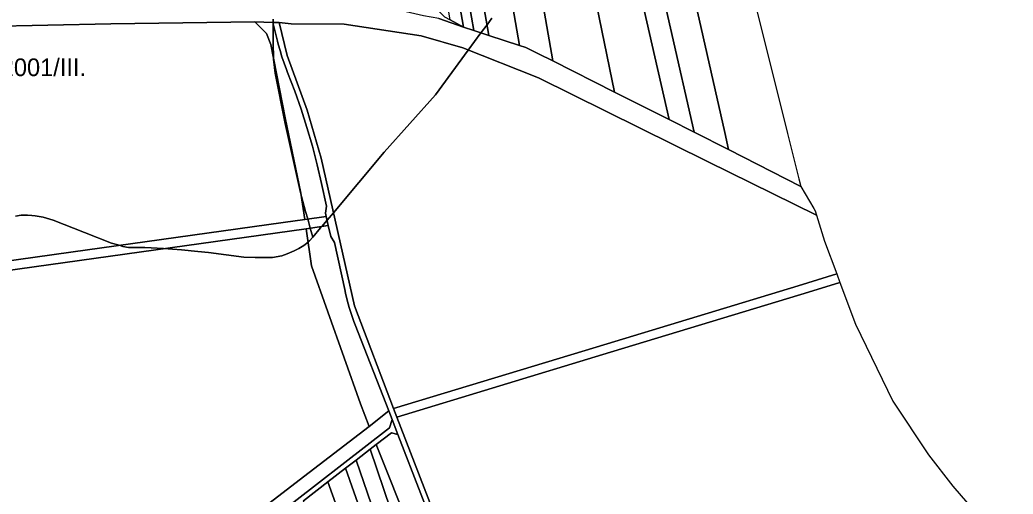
# Model space of a CAD drawing. Extents: x -521939 to -516426, y -1197857 to -1189551.
# Drawn here: x -518732 to -517887, y -1193407 to -1193004 of the extents above; entities that cross this region are included whole.
import ezdxf

# ---------------------------------------------------------------- set-up
doc = ezdxf.new("R2010")
doc.units = 0
for name, color, linetype in [('95560013', 7, 'Continuous'), ('95600013', 7, 'Continuous'), ('95610013', 7, 'Continuous'), ('95640013', 7, 'Continuous'), ('95660013', 7, 'Continuous')]:
    doc.layers.add(name, color=color, linetype=linetype)

msp = doc.modelspace()

# ---------------------------------------------------------------- linework, layer by layer
at = {"layer": '95560013'}
for points in [[(-518037.03, -1193220.36), (-518069.91, -1193230.34), (-518241.69, -1193282.48), (-518414.03, -1193334.79), (-518447.17, -1193247.47), (-518475.5, -1193121.86), (-518487.43, -1193081.14), (-518504.4, -1193034.52), (-518511.04, -1193006.71), (-518500.8, -1193007.81), (-518455.87, -1193008.08), (-518390.51, -1193017.79), (-518355.07, -1193028.15), (-518290.52, -1193053.74), (-518147.01, -1193124.62), (-518054.34, -1193170.39), (-518047.58, -1193192.34)], [(-517920.81, -1193457.64), (-517929.64, -1193459.01), (-517949.48, -1193456.49), (-517956.24, -1193459.13), (-517971.27, -1193470.3), (-517974.13, -1193472.43), (-518004.98, -1193496.63), (-518036.86, -1193524.72), (-518069.66, -1193560.73), (-518084.56, -1193581.03), (-518118.24, -1193594.97), (-518286.06, -1193664.43), (-518346.04, -1193509.88), (-518411.17, -1193342.06), (-518236.07, -1193288.88), (-518060.97, -1193235.7), (-518034.3, -1193227.6), (-518020.98, -1193262.98), (-517989.44, -1193328.34), (-517959.05, -1193374.1), (-517938.3, -1193400.82), (-517925.8, -1193415.15), (-517887.1, -1193453.28), (-517902.58, -1193457.64)], [(-518428.58, -1193365.29), (-518398.79, -1193439.68), (-518355.54, -1193549.59), (-518335.93, -1193621.27), (-518319.66, -1193697.29), (-518316.66, -1193706.74), (-518319.47, -1193708.05), (-518370.33, -1193556.63), (-518433.69, -1193369.25)], [(-518433.69, -1193369.25), (-518370.33, -1193556.63), (-518319.47, -1193708.05), (-518330.65, -1193713.26), (-518387.8, -1193546.85), (-518445.63, -1193378.46)], [(-518387.8, -1193546.85), (-518330.65, -1193713.26), (-518337.92, -1193716.66), (-518394.9, -1193555.25), (-518454.81, -1193385.54), (-518445.63, -1193378.46)], [(-518469.66, -1193396.97), (-518454.81, -1193385.54), (-518394.9, -1193555.25), (-518337.92, -1193716.66), (-518352.46, -1193723.43), (-518407.89, -1193569.03)], [(-518490.41, -1193413.05), (-518469.66, -1193396.97), (-518407.89, -1193569.03), (-518352.46, -1193723.43), (-518374.87, -1193733.88), (-518429.84, -1193581.24)]]:
    msp.add_lwpolyline(points, close=True, dxfattribs=at)
at = {"layer": '95600013'}
for points in [[(-518761.5, -1193009.97), (-518654.27, -1193007.7), (-518531.81, -1193005.92), (-518522.01, -1193015.8), (-518518.32, -1193025.36), (-518505.93, -1193087.66), (-518492.56, -1193151.65), (-518489.33, -1193173.91), (-518507.69, -1193176.48), (-518688.29, -1193201.76), (-518868.39, -1193226.97)], [(-518861.71, -1193234.11), (-518680.88, -1193208.8), (-518488.19, -1193181.83), (-518483.68, -1193213.33), (-518442.04, -1193330.76), (-518434.69, -1193349.86), (-518485.73, -1193389.02), (-518538.28, -1193429.5), (-518577.2, -1193463.96), (-518591.51, -1193476.86), (-518618.18, -1193506.33), (-518639.59, -1193535.59), (-518664.37, -1193572.73), (-518683.73, -1193611.33), (-518704.53, -1193662.76), (-518731.88, -1193727.36)]]:
    msp.add_lwpolyline(points, dxfattribs=at)
at = {"layer": '95610013'}
for points in [[(-518158.26, -1193099.67), (-518198.65, -1192922.73), (-518238.83, -1192746.71), (-518279.01, -1192570.69), (-518261.25, -1192554.36), (-518217.03, -1192728.56), (-518209.44, -1192758.46), (-518173.86, -1192915.92), (-518132.24, -1193100.11), (-518128.95, -1193114.67)], [(-518179.48, -1193089.1), (-518215.17, -1192932.78), (-518254.65, -1192759.86), (-518294.63, -1192584.75), (-518279.01, -1192570.69), (-518238.83, -1192746.71), (-518198.65, -1192922.73), (-518158.26, -1193099.67)], [(-518225.89, -1193065.68), (-518247.64, -1192960.63), (-518284.38, -1192783.18), (-518321.12, -1192605.73), (-518294.63, -1192584.75), (-518254.65, -1192759.86), (-518215.17, -1192932.78), (-518179.48, -1193089.1)], [(-518350.16, -1192628.53), (-518321.12, -1192605.73), (-518284.38, -1192783.18), (-518247.64, -1192960.63), (-518225.89, -1193065.68), (-518278.49, -1193039.24)], [(-518306.65, -1193026.04), (-518372.77, -1192646.35), (-518360.29, -1192636.5), (-518350.16, -1192628.53), (-518278.49, -1193039.24), (-518290.64, -1193033.2), (-518301.5, -1193027.7)], [(-518332.79, -1193017.61), (-518362.85, -1192845.05), (-518394.49, -1192663.42), (-518372.77, -1192646.35), (-518306.65, -1193026.04)], [(-518345.74, -1193013.45), (-518375.39, -1192842.99), (-518405.16, -1192671.84), (-518394.49, -1192663.42), (-518362.85, -1192845.05), (-518332.79, -1193017.61)], [(-518354.48, -1193010.65), (-518381.33, -1192856.31), (-518412.43, -1192677.54), (-518405.16, -1192671.84), (-518375.39, -1192842.99), (-518345.74, -1193013.45)], [(-518421.2, -1192684.43), (-518412.43, -1192677.54), (-518381.33, -1192856.31), (-518354.48, -1193010.65), (-518365.62, -1193004.33), (-518389.89, -1192864.64)], [(-518128.95, -1193114.67), (-518132.24, -1193100.11), (-518173.86, -1192915.92), (-518209.44, -1192758.46), (-518180.89, -1192756.84), (-518178.51, -1192764.73), (-518168.14, -1192787.68), (-518151.23, -1192812.5), (-518135.12, -1192876.72), (-518109.82, -1192977.58), (-518107.93, -1192985.11), (-518095.16, -1193036.02), (-518078.88, -1193100.92), (-518069.18, -1193139.58), (-518067.56, -1193146.04)], [(-518441.46, -1192991.31), (-518473.62, -1192989.89), (-518515.05, -1192990), (-518518.64, -1192955.67), (-518520.44, -1192948.52), (-518525.77, -1192940.63), (-518533.4, -1192935.15), (-518519.63, -1192942.55), (-518502, -1192942.29), (-518494.49, -1192943.25), (-518485.76, -1192945.93), (-518469.02, -1192953.53), (-518442.41, -1192965.03), (-518428.88, -1192969.95), (-518413.6, -1192975.54), (-518404.12, -1192979.78), (-518382.7, -1192989.47), (-518370.63, -1193001.75), (-518365.62, -1193004.33), (-518354.48, -1193010.65), (-518375.31, -1193003.18), (-518388.43, -1193000.81), (-518414.09, -1192994.92)]]:
    msp.add_lwpolyline(points, close=True, dxfattribs=at)
at = {"layer": '95640013'}
for points in [[(-518375.31, -1193003.18), (-518354.48, -1193010.65), (-518345.74, -1193013.45), (-518332.79, -1193017.61), (-518306.65, -1193026.04), (-518301.5, -1193027.7), (-518290.64, -1193033.2), (-518278.49, -1193039.24), (-518225.89, -1193065.68), (-518179.48, -1193089.1), (-518158.26, -1193099.67), (-518128.95, -1193114.67), (-518067.56, -1193146.04), (-518064.02, -1193152.08), (-518056.58, -1193164.78), (-518055.5, -1193166.62), (-518054.34, -1193170.39), (-518147.01, -1193124.62), (-518290.52, -1193053.74), (-518355.07, -1193028.15), (-518390.51, -1193017.79), (-518455.87, -1193008.08), (-518500.8, -1193007.81), (-518511.04, -1193006.71), (-518516.38, -1193006.51), (-518531.81, -1193005.92), (-518654.27, -1193007.7), (-518761.5, -1193009.97)], [(-518371.15, -1193457.53), (-518410.27, -1193356.7), (-518415.16, -1193344.07), (-518417.99, -1193336.8), (-518446.36, -1193263.63), (-518447.5, -1193260.7), (-518449.59, -1193254.77), (-518451.5, -1193248.77), (-518453.21, -1193242.73), (-518454.74, -1193236.63), (-518455.41, -1193233.56), (-518464.15, -1193193.47), (-518467.31, -1193188.37), (-518469.31, -1193179.19), (-518471.02, -1193171.35), (-518471.6, -1193168.66), (-518470.85, -1193162.71), (-518475.05, -1193143.47), (-518478.75, -1193127.52), (-518482.9, -1193111.67), (-518487.47, -1193095.95), (-518492.48, -1193080.35), (-518497.9, -1193064.9), (-518503.94, -1193049.14), (-518504.98, -1193046.52), (-518506.92, -1193041.24), (-518508.71, -1193035.9), (-518510.35, -1193030.52), (-518511.83, -1193025.09), (-518512.5, -1193022.36), (-518516.38, -1193006.51), (-518511.04, -1193006.71), (-518504.4, -1193034.52), (-518487.43, -1193081.14), (-518475.5, -1193121.86), (-518447.17, -1193247.47), (-518414.03, -1193334.79), (-518411.17, -1193342.06), (-518346.04, -1193509.88)], [(-518538.28, -1193429.5), (-518485.73, -1193389.02), (-518434.69, -1193349.86), (-518417.99, -1193336.8), (-518415.16, -1193344.07), (-518417.16, -1193351.25), (-518517.26, -1193428.71)], [(-518517.26, -1193428.71), (-518417.16, -1193351.25), (-518415.16, -1193344.07), (-518410.27, -1193356.7), (-518415.55, -1193355.23), (-518428.58, -1193365.29), (-518433.69, -1193369.25), (-518445.63, -1193378.46), (-518454.81, -1193385.54), (-518469.66, -1193396.97), (-518490.41, -1193413.05)]]:
    msp.add_lwpolyline(points, dxfattribs=at)
for points in [[(-518531.81, -1193005.92), (-518516.38, -1193006.51), (-518512.5, -1193022.36), (-518511.83, -1193025.09), (-518510.35, -1193030.52), (-518508.71, -1193035.9), (-518506.92, -1193041.24), (-518504.98, -1193046.52), (-518503.94, -1193049.14), (-518497.9, -1193064.9), (-518492.48, -1193080.35), (-518487.47, -1193095.95), (-518482.9, -1193111.67), (-518478.75, -1193127.52), (-518475.05, -1193143.47), (-518470.85, -1193162.71), (-518471.6, -1193168.66), (-518471.02, -1193171.35), (-518489.33, -1193173.91), (-518492.56, -1193151.65), (-518505.93, -1193087.66), (-518518.32, -1193025.36), (-518522.01, -1193015.8)], [(-518489.33, -1193173.91), (-518471.02, -1193171.35), (-518469.31, -1193179.19), (-518488.19, -1193181.83), (-518680.88, -1193208.8), (-518861.71, -1193234.11), (-518868.39, -1193226.97), (-518688.29, -1193201.76), (-518507.69, -1193176.48)], [(-518417.99, -1193336.8), (-518434.69, -1193349.86), (-518442.04, -1193330.76), (-518483.68, -1193213.33), (-518488.19, -1193181.83), (-518469.31, -1193179.19), (-518467.31, -1193188.37), (-518464.15, -1193193.47), (-518455.41, -1193233.56), (-518454.74, -1193236.63), (-518453.21, -1193242.73), (-518451.5, -1193248.77), (-518449.59, -1193254.77), (-518447.5, -1193260.7), (-518446.36, -1193263.63)], [(-518034.3, -1193227.6), (-518060.97, -1193235.7), (-518236.07, -1193288.88), (-518411.17, -1193342.06), (-518414.03, -1193334.79), (-518241.69, -1193282.48), (-518069.91, -1193230.34), (-518037.03, -1193220.36)], [(-518280.43, -1193713.43), (-518282.05, -1193724.63), (-518285.29, -1193735.47), (-518301.75, -1193752.95), (-518316.66, -1193706.74), (-518319.66, -1193697.29), (-518335.93, -1193621.27), (-518355.54, -1193549.59), (-518398.79, -1193439.68), (-518428.58, -1193365.29), (-518415.55, -1193355.23), (-518410.27, -1193356.7), (-518371.15, -1193457.53), (-518370.97, -1193463.53), (-518363.68, -1193482.34), (-518359.76, -1193486.89), (-518295.93, -1193654.71), (-518282.15, -1193690.94), (-518280.46, -1193702.12)]]:
    msp.add_lwpolyline(points, close=True, dxfattribs=at)
at = {"layer": '95660013'}
for points in [[(-518107.93, -1192985.11), (-518095.16, -1193036.02), (-518078.88, -1193100.92), (-518069.18, -1193139.58), (-518067.56, -1193146.04), (-518064.02, -1193152.08), (-518056.58, -1193164.78), (-518055.5, -1193166.62), (-518054.34, -1193170.39), (-518047.58, -1193192.34), (-518037.03, -1193220.36), (-518034.3, -1193227.6), (-518020.98, -1193262.98), (-517989.44, -1193328.34), (-517959.05, -1193374.1), (-517938.3, -1193400.82), (-517925.8, -1193415.15)], [(-518735.4, -1193171.07), (-518730.5, -1193170.49), (-518725.13, -1193170.37), (-518721.46, -1193170.63), (-518718.6, -1193170.84), (-518711.72, -1193172.12), (-518703.2, -1193174.69), (-518676.49, -1193185.19), (-518653.63, -1193194.05), (-518647.03, -1193195.98), (-518644.07, -1193196.85), (-518639.17, -1193197.78), (-518628.35, -1193197.83), (-518625.35, -1193197.84), (-518609.39, -1193198.79), (-518594.09, -1193199.71), (-518580.27, -1193201.12), (-518571.22, -1193202.04), (-518541.13, -1193206.01), (-518531.54, -1193206.3), (-518528.66, -1193206.38), (-518525.73, -1193206.47), (-518516.87, -1193206.24), (-518508.71, -1193204.84), (-518504.16, -1193203.27), (-518498.27, -1193200.76), (-518494.36, -1193198.72), (-518490.04, -1193196.09), (-518486.56, -1193193.22), (-518486.08, -1193192.83), (-518485.36, -1193192.07), (-518482.46, -1193189.04), (-518475.86, -1193181.17), (-518474.85, -1193179.96), (-518470.32, -1193174.57), (-518465.03, -1193168.27), (-518421.93, -1193116.89), (-518378.3, -1193068.14), (-518350.28, -1193030.05), (-518339.54, -1193015.44), (-518334.39, -1193008.44), (-518330.25, -1193002.82)], [(-518516.26, -1193003.71), (-518516.26, -1193006.51), (-518516.26, -1193007), (-518516.26, -1193023.54), (-518515.91, -1193037.45), (-518515.91, -1193037.65), (-518514.39, -1193049.78), (-518505.88, -1193092.36), (-518493.08, -1193151.19), (-518492.14, -1193154.53), (-518488.61, -1193167.11), (-518486.8, -1193173.56), (-518484.62, -1193181.33), (-518482.46, -1193189.04), (-518485.36, -1193192.07), (-518486.08, -1193192.83), (-518486.56, -1193193.22), (-518490.04, -1193196.09), (-518494.36, -1193198.72), (-518498.27, -1193200.76), (-518504.16, -1193203.27), (-518508.71, -1193204.84), (-518516.87, -1193206.24), (-518525.73, -1193206.47), (-518528.66, -1193206.38), (-518531.54, -1193206.3), (-518541.13, -1193206.01), (-518571.22, -1193202.04), (-518580.27, -1193201.12), (-518594.09, -1193199.71), (-518609.39, -1193198.79), (-518625.35, -1193197.84), (-518628.35, -1193197.83), (-518639.17, -1193197.78), (-518644.07, -1193196.85), (-518647.03, -1193195.98), (-518653.63, -1193194.05), (-518676.49, -1193185.19), (-518703.2, -1193174.69), (-518711.72, -1193172.12), (-518718.6, -1193170.84), (-518721.46, -1193170.63), (-518725.13, -1193170.37), (-518730.5, -1193170.49), (-518735.4, -1193171.07)], [(-518330.25, -1193002.82), (-518334.39, -1193008.44), (-518339.54, -1193015.44), (-518350.28, -1193030.05), (-518378.3, -1193068.14), (-518421.93, -1193116.89), (-518465.03, -1193168.27), (-518470.32, -1193174.57), (-518474.85, -1193179.96), (-518475.86, -1193181.17), (-518482.46, -1193189.04), (-518484.62, -1193181.33), (-518486.8, -1193173.56), (-518488.61, -1193167.11), (-518492.14, -1193154.53), (-518493.08, -1193151.19), (-518505.88, -1193092.36), (-518514.39, -1193049.78), (-518515.91, -1193037.65), (-518515.91, -1193037.45), (-518516.26, -1193023.54), (-518516.26, -1193007), (-518516.26, -1193006.51), (-518516.26, -1193003.71)]]:
    msp.add_lwpolyline(points, dxfattribs=at)

# ---------------------------------------------------------------- texts
msp.add_text('62001/III.', height=15, rotation=360, dxfattribs=at).set_placement((-518758.94, -1193052.17))

doc.saveas('drawing.dxf')
